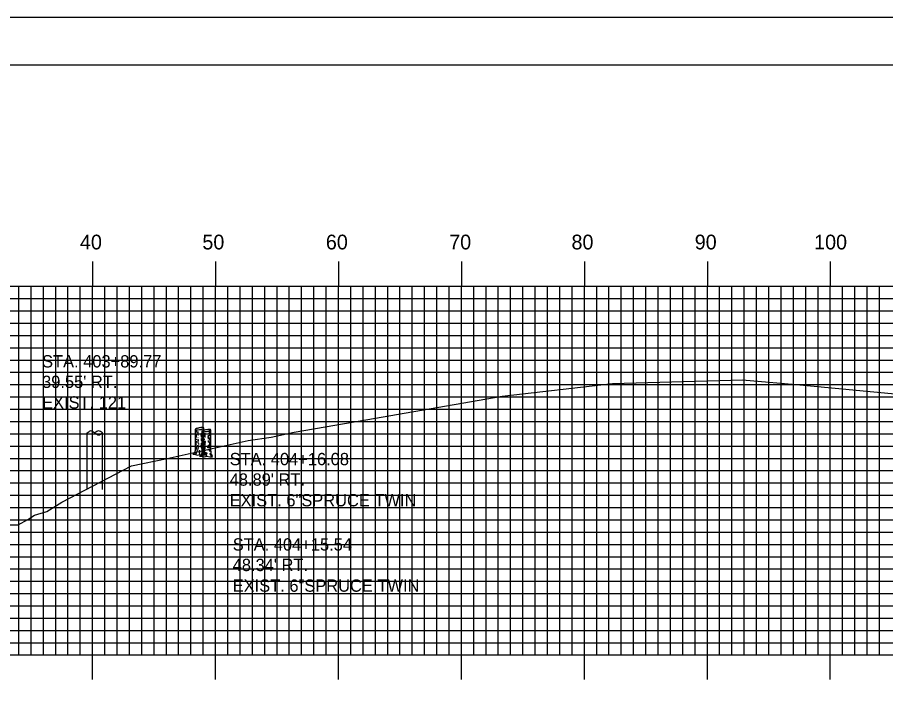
# Model space of a CAD drawing. Extents: x 850955 to 851298, y 364785 to 365005.
# Drawn here: x 851154.6 to 851225.2, y 364950.7 to 365005.1 of the extents above; entities that cross this region are included whole.
import ezdxf

# ---------------------------------------------------------------- set-up
doc = ezdxf.new("R2010")
doc.units = 0
for name, color, linetype in [('BORDER', 7, 'Continuous'), ('D_Text_Monospaced', 7, 'Continuous'), ('H_V ANNOTATION', 7, 'Continuous'), ('MAJOR', 7, 'Continuous'), ('MINOR', 7, 'Continuous'), ('PLOT BOUNDARY', 7, 'Continuous'), ('S_Roadway_Centerline', 7, 'Continuous'), ('S_Trees_Conifer_NonPay', 7, 'Continuous'), ('S_Utilities_Pole_Power', 7, 'Continuous')]:
    doc.layers.add(name, color=color, linetype=linetype)

msp = doc.modelspace()

# ---------------------------------------------------------------- linework, layer by layer
at = {"layer": 'BORDER'}
msp.add_lwpolyline([(850971.078, 364791.233), (851291.078, 364791.233), (851291.078, 365001.233), (850971.078, 365001.233)], close=True, dxfattribs=at)
at = {"layer": 'MAJOR'}
for p, q in [((851160.678, 364985.237), (851160.678, 364983.233)), ((851170.678, 364985.237), (851170.678, 364983.233)), ((851180.678, 364985.237), (851180.678, 364983.233)), ((851190.678, 364985.237), (851190.678, 364983.233)), ((851200.678, 364985.237), (851200.678, 364983.233)), ((851210.678, 364985.237), (851210.678, 364983.233)), ((851220.678, 364985.237), (851220.678, 364983.233)), ((850980.678, 364983.233), (851260.678, 364983.233)), ((850980.678, 364983.233), (851260.678, 364983.233)), ((851160.678, 364953.233), (851160.678, 364983.233)), ((851170.678, 364953.233), (851170.678, 364983.233)), ((851180.678, 364953.233), (851180.678, 364983.233)), ((851190.678, 364953.233), (851190.678, 364983.233)), ((851200.678, 364953.233), (851200.678, 364983.233)), ((851210.678, 364953.233), (851210.678, 364983.233)), ((851220.678, 364953.233), (851220.678, 364983.233)), ((850980.678, 364978.233), (851260.678, 364978.233)), ((850980.678, 364973.233), (851260.678, 364973.233)), ((850980.678, 364968.233), (851260.678, 364968.233)), ((850980.678, 364963.233), (851260.678, 364963.233)), ((850980.678, 364958.233), (851260.678, 364958.233)), ((850980.678, 364953.233), (851260.678, 364953.233)), ((850980.678, 364953.233), (851260.678, 364953.233)), ((851160.678, 364951.229), (851160.678, 364953.233)), ((851170.678, 364951.229), (851170.678, 364953.233)), ((851180.678, 364951.229), (851180.678, 364953.233)), ((851190.678, 364951.229), (851190.678, 364953.233)), ((851200.678, 364951.229), (851200.678, 364953.233)), ((851210.678, 364951.229), (851210.678, 364953.233)), ((851220.678, 364951.229), (851220.678, 364953.233))]:
    msp.add_line(p, q, dxfattribs=at)
at = {"layer": 'MINOR'}
for p, q in [((851154.678, 364953.233), (851154.678, 364983.233)), ((851155.678, 364953.233), (851155.678, 364983.233)), ((851156.678, 364953.233), (851156.678, 364983.233)), ((851157.678, 364953.233), (851157.678, 364983.233)), ((851158.678, 364953.233), (851158.678, 364983.233)), ((851159.678, 364953.233), (851159.678, 364983.233)), ((851161.678, 364953.233), (851161.678, 364983.233)), ((851162.678, 364953.233), (851162.678, 364983.233)), ((851163.678, 364953.233), (851163.678, 364983.233)), ((851164.678, 364953.233), (851164.678, 364983.233)), ((851165.678, 364953.233), (851165.678, 364983.233)), ((851166.678, 364953.233), (851166.678, 364983.233)), ((851167.678, 364953.233), (851167.678, 364983.233)), ((851168.678, 364953.233), (851168.678, 364983.233)), ((851169.678, 364953.233), (851169.678, 364983.233)), ((851171.678, 364953.233), (851171.678, 364983.233)), ((851172.678, 364953.233), (851172.678, 364983.233)), ((851173.678, 364953.233), (851173.678, 364983.233)), ((851174.678, 364953.233), (851174.678, 364983.233)), ((851175.678, 364953.233), (851175.678, 364983.233)), ((851176.678, 364953.233), (851176.678, 364983.233)), ((851177.678, 364953.233), (851177.678, 364983.233)), ((851178.678, 364953.233), (851178.678, 364983.233)), ((851179.678, 364953.233), (851179.678, 364983.233)), ((851181.678, 364953.233), (851181.678, 364983.233)), ((851182.678, 364953.233), (851182.678, 364983.233)), ((851183.678, 364953.233), (851183.678, 364983.233)), ((851184.678, 364953.233), (851184.678, 364983.233)), ((851185.678, 364953.233), (851185.678, 364983.233)), ((851186.678, 364953.233), (851186.678, 364983.233)), ((851187.678, 364953.233), (851187.678, 364983.233)), ((851188.678, 364953.233), (851188.678, 364983.233)), ((851189.678, 364953.233), (851189.678, 364983.233)), ((851191.678, 364953.233), (851191.678, 364983.233)), ((851192.678, 364953.233), (851192.678, 364983.233)), ((851193.678, 364953.233), (851193.678, 364983.233)), ((851194.678, 364953.233), (851194.678, 364983.233)), ((851195.678, 364953.233), (851195.678, 364983.233)), ((851196.678, 364953.233), (851196.678, 364983.233)), ((851197.678, 364953.233), (851197.678, 364983.233)), ((851198.678, 364953.233), (851198.678, 364983.233)), ((851199.678, 364953.233), (851199.678, 364983.233)), ((851201.678, 364953.233), (851201.678, 364983.233)), ((851202.678, 364953.233), (851202.678, 364983.233)), ((851203.678, 364953.233), (851203.678, 364983.233)), ((851204.678, 364953.233), (851204.678, 364983.233)), ((851205.678, 364953.233), (851205.678, 364983.233)), ((851206.678, 364953.233), (851206.678, 364983.233)), ((851207.678, 364953.233), (851207.678, 364983.233)), ((851208.678, 364953.233), (851208.678, 364983.233)), ((851209.678, 364953.233), (851209.678, 364983.233)), ((851211.678, 364953.233), (851211.678, 364983.233)), ((851212.678, 364953.233), (851212.678, 364983.233)), ((851213.678, 364953.233), (851213.678, 364983.233)), ((851214.678, 364953.233), (851214.678, 364983.233)), ((851215.678, 364953.233), (851215.678, 364983.233)), ((851216.678, 364953.233), (851216.678, 364983.233)), ((851217.678, 364953.233), (851217.678, 364983.233)), ((851218.678, 364953.233), (851218.678, 364983.233)), ((851219.678, 364953.233), (851219.678, 364983.233)), ((851221.678, 364953.233), (851221.678, 364983.233)), ((851222.678, 364953.233), (851222.678, 364983.233)), ((851223.678, 364953.233), (851223.678, 364983.233)), ((851224.678, 364953.233), (851224.678, 364983.233)), ((850980.678, 364982.233), (851260.678, 364982.233)), ((850980.678, 364981.233), (851260.678, 364981.233)), ((850980.678, 364980.233), (851260.678, 364980.233)), ((850980.678, 364979.233), (851260.678, 364979.233)), ((850980.678, 364977.233), (851260.678, 364977.233)), ((850980.678, 364976.233), (851260.678, 364976.233)), ((850980.678, 364975.233), (851260.678, 364975.233)), ((850980.678, 364974.233), (851260.678, 364974.233)), ((850980.678, 364972.233), (851260.678, 364972.233)), ((850980.678, 364971.233), (851260.678, 364971.233)), ((850980.678, 364970.233), (851260.678, 364970.233)), ((850980.678, 364969.233), (851260.678, 364969.233)), ((850980.678, 364967.233), (851260.678, 364967.233)), ((850980.678, 364966.233), (851260.678, 364966.233)), ((850980.678, 364965.233), (851260.678, 364965.233)), ((850980.678, 364964.233), (851260.678, 364964.233)), ((850980.678, 364962.233), (851260.678, 364962.233)), ((850980.678, 364961.233), (851260.678, 364961.233)), ((850980.678, 364960.233), (851260.678, 364960.233)), ((850980.678, 364959.233), (851260.678, 364959.233)), ((850980.678, 364957.233), (851260.678, 364957.233)), ((850980.678, 364956.233), (851260.678, 364956.233)), ((850980.678, 364955.233), (851260.678, 364955.233)), ((850980.678, 364954.233), (851260.678, 364954.233))]:
    msp.add_line(p, q, dxfattribs=at)
at = {"layer": 'PLOT BOUNDARY'}
msp.add_lwpolyline([(850954.892, 364785.114), (851294.892, 364785.114), (851294.892, 365005.114), (850954.892, 365005.114)], close=True, dxfattribs=at)
at = {"layer": 'S_Roadway_Centerline'}
msp.add_lwpolyline([(851153.684, 364963.835), (851154.619, 364963.824), (851155.407, 364964.253), (851155.967, 364964.61), (851156.949, 364964.913), (851158.168, 364965.68), (851163.84, 364968.621), (851166.745, 364969.221), (851173.342, 364970.672), (851175.196, 364970.947), (851177.072, 364971.371), (851182.913, 364972.366), (851193.979, 364974.299), (851202.956, 364975.312), (851213.533, 364975.616), (851218.509, 364975.183), (851226.796, 364974.39), (851231.263, 364974.277), (851239.228, 364974.829), (851250.395, 364975.591), (851251.623, 364975.668), (851254.103, 364975.761), (851260.678, 364975.991)], dxfattribs=at)
at = {"layer": 'S_Trees_Conifer_NonPay'}
for p, q in [((851169.094, 364971.546), (851169.094, 364971.34)), ((851169.094, 364971.267), (851169.094, 364970.936)), ((851169.251, 364971.421), (851169.251, 364971.147)), ((851169.513, 364971.601), (851169.513, 364971.522)), ((851169.513, 364971.273), (851169.513, 364970.947)), ((851169.647, 364971.398), (851169.647, 364971.192)), ((851169.647, 364971.312), (851169.647, 364971.182)), ((851169.647, 364971.119), (851169.647, 364970.788)), ((851169.804, 364971.273), (851169.804, 364970.999)), ((851170.066, 364971.453), (851170.066, 364971.374)), ((851170.066, 364971.125), (851170.066, 364970.799)), ((851170.2, 364971.164), (851170.2, 364971.033)), ((851169.077, 364970.442), (851169.077, 364970.345)), ((851169.094, 364970.822), (851169.094, 364970.743)), ((851169.094, 364970.629), (851169.094, 364970.519)), ((851169.251, 364970.794), (851169.251, 364970.475)), ((851169.292, 364970.431), (851169.292, 364970.361)), ((851169.513, 364970.846), (851169.513, 364970.693)), ((851169.513, 364970.464), (851169.513, 364970.231)), ((851169.647, 364971.073), (851169.647, 364970.846)), ((851169.647, 364970.754), (851169.647, 364970.378)), ((851169.647, 364970.674), (851169.647, 364970.595)), ((851169.647, 364970.481), (851169.647, 364970.371)), ((851169.804, 364970.646), (851169.804, 364970.327)), ((851170.066, 364970.698), (851170.066, 364970.545)), ((851170.2, 364970.925), (851170.2, 364970.698)), ((851170.2, 364970.606), (851170.2, 364970.23)), ((851169.094, 364970.231), (851169.094, 364969.963)), ((851169.251, 364970.306), (851169.251, 364970.146)), ((851169.251, 364970.088), (851169.251, 364969.957)), ((851169.513, 364970.168), (851169.513, 364970.082)), ((851169.629, 364970.185), (851169.646, 364969.94)), ((851169.63, 364970.294), (851169.63, 364970.197)), ((851169.647, 364970.083), (851169.647, 364969.815)), ((851169.708, 364969.957), (851169.768, 364969.964)), ((851169.804, 364970.157), (851169.804, 364969.998)), ((851169.804, 364969.94), (851169.804, 364969.809)), ((851169.845, 364970.283), (851169.845, 364970.213)), ((851170.066, 364970.316), (851170.066, 364970.083)), ((851170.066, 364970.02), (851170.066, 364969.934)), ((851170.182, 364970.037), (851170.199, 364969.792)), ((851170.261, 364969.809), (851170.321, 364969.816))]:
    msp.add_line(p, q, dxfattribs=at)
for points in [[(851169.015, 364971.58), (851169.015, 364969.862), (851168.946, 364969.605), (851168.826, 364969.571), (851169.043, 364969.555), (851169.202, 364969.496), (851169.412, 364969.555), (851169.674, 364969.508), (851169.88, 364969.514), (851169.729, 364969.617), (851169.657, 364969.77)], [(851169.569, 364971.432), (851169.569, 364969.714), (851169.499, 364969.457), (851169.38, 364969.423), (851169.596, 364969.407), (851169.756, 364969.348), (851169.965, 364969.407), (851170.227, 364969.36), (851170.433, 364969.365), (851170.282, 364969.469), (851170.21, 364969.622)], [(851169.647, 364971.641), (851169.647, 364971.544), (851169.647, 364971.38)], [(851169.758, 364969.596), (851169.874, 364969.605), (851169.782, 364969.731), (851169.749, 364970.271), (851169.729, 364970.788), (851169.729, 364971.708)], [(851170.2, 364971.493), (851170.2, 364971.396), (851170.2, 364971.232)], [(851170.311, 364969.448), (851170.427, 364969.457), (851170.336, 364969.583), (851170.302, 364970.123), (851170.282, 364970.64), (851170.282, 364971.56)], [(851169.043, 364969.555), (851169.133, 364969.667), (851169.15, 364969.781)], [(851169.174, 364969.918), (851169.163, 364969.873), (851169.214, 364969.862), (851169.214, 364969.924)], [(851169.412, 364969.555), (851169.367, 364969.731), (851169.361, 364969.895)], [(851169.365, 364969.781), (851169.435, 364969.775), (851169.453, 364969.828)], [(851169.727, 364969.77), (851169.716, 364969.725), (851169.767, 364969.714), (851169.767, 364969.776)], [(851169.965, 364969.407), (851169.92, 364969.583), (851169.914, 364969.747)], [(851169.596, 364969.407), (851169.686, 364969.519), (851169.703, 364969.633)], [(851169.918, 364969.633), (851169.988, 364969.627), (851170.006, 364969.68)]]:
    msp.add_lwpolyline(points, dxfattribs=at)
for centre, radius, start, end in [((851169.034, 364971.579), 0.0186, 160.37984, 174.32667), ((851169.029, 364971.58), 0.0141, 174.32667, 190.37984), ((851169.041, 364971.577), 0.0263, 141.61947, 160.37984), ((851169.029, 364971.58), 0.0141, 190.37984, 206.43302), ((851169.03, 364971.464), 0.0143, 180, 196.05154), ((851169.033, 364971.582), 0.0186, 206.43302, 220.37984), ((851169.039, 364971.587), 0.0263, 220.37984, 239.14022), ((851169.078, 364971.548), 0.0729, 130.37984, 141.61947), ((851169.063, 364971.627), 0.0729, 239.14022, 250.37984), ((851169.189, 364971.417), 0.245, 108.39459, 130.37984), ((851169.121, 364971.789), 0.245, 250.37984, 272.3651), ((851169.16, 364971.4), 0.245, 244.31482, 257.53746), ((851169.158, 364971.653), 0.245, 254.84608, 261.8968), ((851169.688, 364969.917), 1.825, 100.37984, 108.39459), ((851169.372, 364973.16), 1.767, 261.8968, 262.60496), ((851169.056, 364973.368), 1.825, 272.3651, 280.37984), ((851169.372, 364973.16), 1.767, 264.32674, 266.04993), ((851169.374, 364972.908), 1.767, 265.89912, 267.59618), ((851169.688, 364969.917), 1.825, 92.3651, 100.37984), ((851169.056, 364973.368), 1.825, 280.37984, 288.39459), ((851169.374, 364972.908), 1.767, 272.72212, 274.48467), ((851169.372, 364973.16), 1.767, 276.24487, 278.1032), ((851169.582, 364971.432), 0.0141, 174.32667, 190.37984), ((851169.594, 364971.429), 0.0263, 141.61947, 160.37984), ((851169.587, 364971.431), 0.0186, 160.37984, 174.32667), ((851169.582, 364971.432), 0.0141, 190.37984, 206.43302), ((851169.583, 364971.316), 0.0143, 180, 196.05154), ((851169.587, 364971.434), 0.0186, 206.43302, 220.37984), ((851169.592, 364971.439), 0.0263, 220.37984, 239.14022), ((851169.631, 364971.4), 0.0729, 130.37984, 141.61947), ((851169.616, 364971.479), 0.0729, 239.14022, 250.37984), ((851169.742, 364971.269), 0.245, 108.39459, 130.37984), ((851169.674, 364971.641), 0.245, 250.37984, 272.3651), ((851169.623, 364971.496), 0.245, 70.37984, 92.3651), ((851169.587, 364971.653), 0.245, 278.1032, 284.18592), ((851169.554, 364971.869), 0.245, 288.39459, 310.37984), ((851169.711, 364971.505), 0.245, 254.84608, 261.8968), ((851170.241, 364969.769), 1.825, 100.37984, 108.39459), ((851169.926, 364973.012), 1.767, 261.8968, 262.60496), ((851169.587, 364971.653), 0.245, 291.76535, 300), ((851169.609, 364973.22), 1.825, 272.3651, 280.37984), ((851169.681, 364971.658), 0.0729, 59.14022, 70.37984), ((851169.672, 364971.505), 0.0738, 300, 311.25059), ((851169.666, 364971.737), 0.0729, 310.37984, 321.61947), ((851169.704, 364971.698), 0.0263, 40.37984, 59.14022), ((851169.704, 364971.469), 0.0267, 311.25059, 330), ((851169.703, 364971.708), 0.0263, 321.61947, 340.37984), ((851169.705, 364971.217), 0.0267, 311.25059, 330), ((851169.71, 364971.703), 0.0186, 26.43302, 40.37984), ((851169.714, 364971.705), 0.0141, 10.37984, 26.43302), ((851169.71, 364971.706), 0.0186, 340.37984, 354.32667), ((851169.71, 364971.465), 0.0189, 330, 343.94846), ((851169.714, 364971.705), 0.0141, 354.32667, 10.37984), ((851169.712, 364971.213), 0.0189, 330, 343.94846), ((851169.926, 364973.012), 1.767, 264.32674, 266.04993), ((851170.241, 364969.769), 1.825, 92.3651, 100.37984), ((851169.609, 364973.22), 1.825, 280.37984, 288.39459), ((851169.926, 364973.012), 1.767, 276.24487, 278.1032), ((851170.176, 364971.348), 0.245, 70.37984, 92.3651), ((851170.14, 364971.505), 0.245, 278.1032, 284.18592), ((851170.108, 364971.721), 0.245, 288.39459, 310.37984), ((851170.14, 364971.505), 0.245, 291.76535, 300), ((851170.234, 364971.51), 0.0729, 59.14022, 70.37984), ((851170.226, 364971.357), 0.0738, 300, 311.25059), ((851170.219, 364971.589), 0.0729, 310.37984, 321.61947), ((851170.258, 364971.55), 0.0263, 40.37984, 59.14022), ((851170.257, 364971.321), 0.0267, 311.25059, 330), ((851170.256, 364971.56), 0.0263, 321.61947, 340.37984), ((851170.263, 364971.555), 0.0186, 26.43302, 40.37984), ((851170.268, 364971.557), 0.0141, 10.37984, 26.43302), ((851170.263, 364971.317), 0.0189, 330, 343.94846), ((851170.268, 364971.557), 0.0141, 354.32667, 10.37984), ((851170.263, 364971.558), 0.0186, 340.37984, 354.32667), ((851169.03, 364970.998), 0.0143, 180, 196.05154), ((851169.035, 364970.999), 0.0189, 196.05154, 210), ((851169.03, 364970.787), 0.0143, 180, 196.05154), ((851169.035, 364970.788), 0.0189, 196.05155, 210), ((851169.041, 364971.003), 0.0267, 210, 228.74941), ((851169.042, 364970.792), 0.0267, 210, 228.74941), ((851169.072, 364971.039), 0.0738, 228.74941, 240), ((851169.073, 364970.827), 0.0738, 228.74941, 240), ((851169.158, 364971.187), 0.245, 240, 246.79138), ((851169.158, 364970.975), 0.245, 240, 254.95138), ((851169.158, 364971.187), 0.245, 254.84608, 257.54539), ((851169.157, 364970.756), 0.245, 254.98136, 261.8968), ((851169.372, 364972.263), 1.767, 261.8968, 262.44996), ((851169.372, 364972.694), 1.767, 265.22845, 266.13254), ((851169.373, 364972.483), 1.767, 266.04293, 268.55249), ((851169.373, 364972.483), 1.767, 274.53608, 277.00259), ((851169.583, 364970.85), 0.0143, 180, 196.05154), ((851169.584, 364970.639), 0.0143, 180, 196.05154), ((851169.588, 364970.851), 0.0189, 196.05154, 210), ((851169.588, 364970.64), 0.0189, 196.05155, 210), ((851169.594, 364970.855), 0.0267, 210, 228.74941), ((851169.595, 364970.644), 0.0267, 210, 228.74941), ((851169.626, 364970.891), 0.0738, 228.74941, 240), ((851169.626, 364970.679), 0.0738, 228.74941, 240), ((851169.372, 364972.263), 1.767, 276.79664, 278.1032), ((851169.711, 364971.038), 0.245, 240, 246.79138), ((851169.711, 364970.827), 0.245, 240, 254.95138), ((851169.713, 364971.252), 0.245, 244.31482, 257.53746), ((851169.587, 364970.756), 0.245, 278.1032, 284.32068), ((851169.587, 364971.187), 0.245, 284.18592, 300), ((851169.711, 364971.038), 0.245, 254.84608, 257.54539), ((851169.587, 364970.975), 0.245, 292.1924, 300), ((851169.672, 364971.039), 0.0738, 300, 311.25059), ((851169.673, 364970.827), 0.0738, 300, 311.25059), ((851169.704, 364971.003), 0.0267, 311.25059, 330), ((851169.704, 364970.792), 0.0267, 311.25059, 330), ((851169.71, 364970.999), 0.0189, 330, 343.94846), ((851169.71, 364970.788), 0.0189, 330, 343.94846), ((851169.926, 364972.546), 1.767, 265.22845, 266.13254), ((851169.927, 364972.76), 1.767, 265.89912, 267.59618), ((851169.926, 364972.335), 1.767, 266.04293, 268.55249), ((851169.927, 364972.76), 1.767, 272.72212, 274.48467), ((851169.926, 364972.335), 1.767, 274.53608, 277.00259), ((851170.14, 364971.038), 0.245, 284.18592, 300), ((851170.14, 364970.827), 0.245, 292.1924, 300), ((851170.226, 364970.891), 0.0738, 300, 311.25059), ((851170.226, 364970.679), 0.0738, 300, 311.25059), ((851170.257, 364970.855), 0.0267, 311.25059, 330), ((851170.257, 364970.644), 0.0267, 311.25059, 330), ((851170.258, 364971.069), 0.0267, 311.25059, 330), ((851170.263, 364970.851), 0.0189, 330, 343.94846), ((851170.264, 364970.64), 0.0189, 330, 343.94846), ((851170.265, 364971.065), 0.0189, 330, 343.94846), ((851169.03, 364970.35), 0.0143, 180, 196.05154), ((851169.029, 364970.145), 0.0143, 180, 196.05154), ((851169.033, 364970.146), 0.0189, 196.05154, 210), ((851169.04, 364970.15), 0.0267, 210, 228.74941), ((851169.071, 364970.185), 0.0738, 228.74941, 240), ((851169.157, 364970.333), 0.245, 240, 249.16746), ((851169.372, 364972.046), 1.767, 262.26222, 265.04961), ((851169.371, 364971.841), 1.767, 266.08616, 268.21869), ((851169.372, 364972.046), 1.767, 272.62928, 274.56121), ((851169.371, 364971.841), 1.767, 274.27758, 276.30056), ((851169.583, 364970.202), 0.0143, 180, 196.05154), ((851169.582, 364969.996), 0.0143, 180, 196.05154), ((851169.587, 364969.998), 0.0189, 196.05154, 210), ((851169.593, 364970.002), 0.0267, 210, 228.74941), ((851169.624, 364970.037), 0.0738, 228.74941, 240), ((851169.71, 364970.185), 0.245, 240, 249.16746), ((851169.372, 364972.046), 1.767, 277.63004, 278.1032), ((851169.587, 364970.539), 0.245, 278.1032, 294.60559), ((851169.586, 364970.333), 0.245, 284.06839, 300), ((851169.71, 364970.608), 0.245, 254.98136, 261.8968), ((851169.925, 364972.115), 1.767, 261.8968, 262.44996), ((851169.925, 364971.898), 1.767, 262.26222, 265.04961), ((851169.671, 364970.185), 0.0738, 300, 302.05002), ((851169.924, 364971.692), 1.767, 266.08616, 268.21869), ((851169.925, 364971.898), 1.767, 272.62928, 274.56121), ((851169.924, 364971.692), 1.767, 274.27758, 276.30056), ((851169.925, 364972.115), 1.767, 276.79664, 278.1032), ((851169.925, 364971.898), 1.767, 277.63004, 278.1032), ((851170.14, 364970.608), 0.245, 278.1032, 284.32068), ((851170.14, 364970.391), 0.245, 278.1032, 294.60559), ((851170.139, 364970.185), 0.245, 284.06839, 300), ((851170.224, 364970.037), 0.0738, 300, 302.05002)]:
    msp.add_arc(centre, radius, start, end, dxfattribs=at)
at = {"layer": 'S_Utilities_Pole_Power'}
for p, q in [((851160.233, 364966.687), (851160.23, 364971.307)), ((851160.233, 364971.307), (851160.389, 364971.417)), ((851160.701, 364971.417), (851160.858, 364971.307)), ((851161.014, 364971.417), (851160.858, 364971.307)), ((851160.858, 364971.307), (851161.014, 364971.196)), ((851161.483, 364971.307), (851161.327, 364971.417)), ((851161.327, 364971.196), (851161.483, 364971.307)), ((851161.483, 364966.687), (851161.48, 364971.307))]:
    msp.add_line(p, q, dxfattribs=at)
for centre, start, end in [((851160.545, 364971.196), 90, 125.26439), ((851160.545, 364971.196), 54.73561, 90), ((851161.17, 364971.196), 90, 125.26439), ((851161.17, 364971.417), 234.73561, 270), ((851161.17, 364971.196), 54.73561, 90), ((851161.17, 364971.417), 270, 305.26439)]:
    msp.add_arc(centre, 0.271, start, end, dxfattribs=at)

# ---------------------------------------------------------------- texts
at = {"layer": 'D_Text_Monospaced'}
for s, height, p in [('STA. 403+89.77', 0.99996, (851156.571, 364976.629)), ("39.55' RT.", 1, (851156.571, 364974.961)), ('EXIST. 121', 1, (851156.571, 364973.281)), ('STA. 404+16.08', 0.99996, (851171.829, 364968.676)), ("48.89' RT.", 1, (851171.829, 364967.008)), ('EXIST. 6"SPRUCE TWIN', 0.99996, (851171.829, 364965.328)), ('STA. 404+15.54', 0.99996, (851172.075, 364961.728)), ("48.34' RT.", 1, (851172.075, 364960.06)), ('EXIST. 6"SPRUCE TWIN', 0.99996, (851172.075, 364958.38))]:
    msp.add_text(s, height=height, dxfattribs=at).set_placement(p)
at = {"layer": 'H_V ANNOTATION'}
for s, p in [('40', (851159.651, 364986.233)), ('50', (851169.608, 364986.233)), ('60', (851179.651, 364986.233)), ('70', (851189.683, 364986.233)), ('80', (851199.629, 364986.233)), ('90', (851209.651, 364986.233)), ('100', (851219.362, 364986.233))]:
    msp.add_text(s, height=1.2, dxfattribs=at).set_placement(p)

doc.saveas('drawing.dxf')
